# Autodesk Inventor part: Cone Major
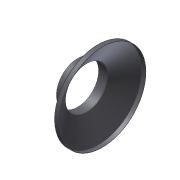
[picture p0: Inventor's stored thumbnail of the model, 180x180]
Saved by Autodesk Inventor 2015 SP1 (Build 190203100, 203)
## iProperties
Category: Mechanical Engineering Drawing and Design - CADD
Manager: Fábio Ricardo de Oliveira Souza
Company: SENAI - Serviço Nacional de Aprendizagem Industrial
Created: 2011-06
Part Number: Cone Major
Material: Steel
Description: Stainless Steel (DIN- X6CrNiTi18-10)
Document SubType Name: Modeling
Designer: Guilherme Augusto Franco de Souza
Engineer: George Geraldo de Oliveia Silva
Authority: Fábio Ricardo de Oliveira Soza
Density: 7.85 g/cm^3
Mass: 689.761 g
Surface Area: 1771.3 cm^2
Volume: 87.8676 cm^3
Appearance: Machined 02
Subject: WorldSkill 2011 - London, England
Author: Guilherme Augusto Franco de Souza
Revision Number: 00
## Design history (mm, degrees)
derived "Cone.ipt"
body "Solid2"
feature "Solid2::Cone.ipt"
tag "TaggingFeature1"
other parameters: "d8" = 1, "d9" = 1, "d10" = 2, "Diam_menor" = 146, "d5" = 15
